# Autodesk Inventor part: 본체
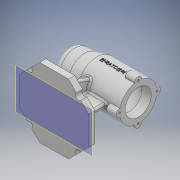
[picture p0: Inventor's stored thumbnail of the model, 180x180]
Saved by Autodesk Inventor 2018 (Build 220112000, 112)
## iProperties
Created: 2019-12
Part Number: 본체
Material: Generic
Document SubType Name: Modeling
Designer: Administrator
Density: 1 g/cm^3
Appearance: Default
Author: Administrator
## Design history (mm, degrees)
sketch "스케치1"
  geometry: L1 (0, 0)-(112, 0); L2 (0, 0)-(0, 25); L3 (0, 25)-(25, 25); L4 (25, 25)-(45, 30); L5 (45, 30)-(112, 30); L6 (112, 30)-(112, 0)
  constraints: 12 end point, 2 perpendicular, 1 horizontal, 1 parallel, 1 vertical
  dimensions: "d0" = 112 distance of L1.start L1.end; "d1" = 25 distance of L1.start L2.end; "d2" = 25 distance of L2.end L3.end; "d3" = 60 diameter of L5 L1; "d4" = 45 distance from line of L4.end L2
revolve "회전1" sketch "스케치1" stored, may be unused: angle "d5" = 90 deg
sketch "스케치2"
  geometry: L1 (112, -30)-(112, 30) reference; L2 (112, 0)-(97, 0); L3 (97, 0)-(97, 21); L4 (97, 21)-(112, 21); L5 (112, 21)-(112, 0); L6 (97, 0)-(43, 0); L7 (43, 0)-(43, 24); L8 (43, 24)-(97, 24); L9 (97, 24)-(97, 0); L10 (43, 0)-(31, 0); L11 (31, 0)-(31, 21); L12 (31, 21)-(43, 21); L13 (43, 21)-(43, 0); L14 (31, 0)-(13, 0); L15 (13, 0)-(13, 17.5); L16 (13, 17.5)-(31, 17.5); L17 (31, 17.5)-(31, 0); L18 (13, 0)-(9, 0); L19 (9, 0)-(9, 16); L20 (9, 16)-(13, 16); L21 (13, 16)-(13, 0); L22 (9, 0)-(6, 0); L23 (6, 0)-(6, 10.5); L24 (6, 10.5)-(9, 10.5); L25 (9, 10.5)-(9, 0); 1 further point
  constraints: 48 end point, 12 parallel, 6 horizontal, 6 perpendicular, 1 midpoint
  dimensions: "d6" = 42 diameter of L4 L2; "d7" = 48 diameter of L8 L6; "d8" = 42 diameter of L12 L10; "d9" = 35 diameter of L16 L14; "d10" = 32 diameter of L20 L18; "d11" = 21 diameter of L24 L22; "d12" = 54 distance between parallel lines of L3 L13; "d13" = 15 distance between parallel lines of L3 L1; "d14" = 12 distance between parallel lines of L13 L17; "d15" = 18 distance between parallel lines of L17 L21; "d16" = 3 distance of L23.end L24.end; "d17" = 4 distance of L19.end L20.end
revolve "회전2" sketch "스케치2" stored, may be unused: angle "d18" = 90 deg
node "작업 평면1"
sketch "스케치3"
  geometry: L1 (-112, 30)-(-112, -30) reference; L2 (-112, 23.196)-(-79.196, 56); L3 (-79.196, 56)-(-32.804, 56); L4 (-32.804, 56)-(0, 23.196); L5 (0, 23.196)-(0, -23.196); L6 (0, -23.196)-(-32.804, -56); L7 (-32.804, -56)-(-79.196, -56); L8 (-79.196, -56)-(-112, -23.196); L9 (-112, -23.196)-(-112, 23.196); C1 r 56 at (-56, 0); 3 further points
  constraints: 16 end point, 2 midpoint, 1 centre point, 1 coincident, 1 tangent, 17 other
  dimensions: "d20" = 112 diameter of C1
extrude "돌출1" join sketch "스케치3" distance "d21" = 10; taper "d22" = 0 deg
sketch "스케치5"
  geometry: C1 r 6 at (0, 30); C2 r 6 at (30, 0); C3 r 6 at (0, -30); C4 r 6 at (-30, 0); A1 r 30 centre (0, 0) between (0, 30) and (30, 0) reference; 1 further point
  constraints: 4 centre point, 4 point on circle
  dimensions: "d27" = 12 diameter of C1; "d28" = 12 diameter of C2; "d29" = 12 diameter of C3; "d30" = 12 diameter of C4
extrude "돌출2" join sketch "스케치5" distance "d31" = 16; taper "d32" = 0 deg
node "작업 평면2"
sketch "스케치6"
  geometry: L1 (-70, 56)-(-70, 23.196) reference; L2 (-70, 56)-(-70, 36); L3 (-70, -56)-(-70, -36); L4 (-70, -56)-(-70, -23.196) reference; L5 (-70, 36)-(-23.234, 18.979); L6 (-70, -36)-(-23.234, -18.979); L7 (-70, -36)-(-70, 36); L8 (-70, 23.196)-(-70, 56) reference; A1 r 30 centre (0, 0) between (-23.234, 18.979) and (-23.234, -18.979); 2 further points
  constraints: 10 end point, 2 point on circle, 2 point on line, 1 centre point, 1 coincident, 1 collinear
  dimensions: "d34" = 20 distance of L1.start L2.end; "d35" = 20 distance of L3.start L3.end; "d37" = 110 deg angle of L1 L5; "d38" = 110 deg angle of L3 L6; "d39" = 60 diameter of A1
extrude "돌출3" join sketch "스케치6" stored distance "d40" = 8; taper "d41" = 0 deg
sketch "스케치7"
  geometry: L1 (60, 36)-(60, -36) reference; L2 (60, 4)-(91, 4); L3 (60, -4)-(91, -4); L4 (91, -4)-(91, 4); L5 (60, -4)-(60, 4); 1 further point
  constraints: 8 end point, 1 collinear, 1 perpendicular
extrude "돌출4" join sketch "스케치7" stored distance "d45" = 8; taper "d46" = 0 deg
sketch "스케치9"
  geometry: L1 (0, -80)-(0, -70) reference; L2 (0, -70)-(32.804, -70) reference; L3 (18, -70)-(37.712, -27.727); L4 (18, -70)-(52, -70); 1 further point
  constraints: 4 end point, 1 horizontal, 1 point on line
  dimensions: "d47" = 18 distance of L1.end L3.start; "d49" = 115 deg angle of L2 L3
feature "리브1" sketch "스케치9" dims "d50" = 1, "d51" = 8, "d52" = 0, "d53" = 0, "d54" = 1, "d55" = 1
fillet "모깎기1" dims "d56" = 10
fillet "모깎기2" dims "d57" = 1
fillet "모깎기3" dims "d58" = 3
sketch "스케치10"
  geometry: L1 (112, -23.196)-(79.196, -56) reference; L2 (32.804, -56)-(0, -23.196) reference; L3 (0, 23.196)-(32.804, 56) reference; L4 (79.196, 56)-(112, 23.196) reference; C1 r 5 at (95.598, -39.598); C2 r 5 at (16.402, -39.598); C3 r 5 at (16.402, 39.598); C4 r 5 at (95.598, 39.598); 1 further point
  constraints: 4 centre point, 4 midpoint
  dimensions: "d59" = 10 diameter of C1; "d60" = 10 diameter of C2; "d61" = 10 diameter of C3; "d62" = 10 diameter of C4
extrude "돌출5" cut sketch "스케치10" distance "d63" = 10; taper "d64" = 0 deg
node "작업 평면3"
sketch "스케치12"
  geometry: L1 (112, 6)-(112, -6) reference; L2 (112, 0)-(71, 0); 4 further points
  constraints: 2 end point, 1 coincident, 1 horizontal, 1 midpoint, 1 other
  dimensions: "d66" = 41 distance of L2.start L2.end
sketch "스케치13"
  geometry: A1 r 5 centre (30, 30) between (34.983, 29.583) and (25.017, 29.583) reference; A2 r 5 centre (0, 0) between (0.417, 4.983) and (0.417, -4.983) reference; A3 r 6 centre (60, 0) between (59.4, -5.97) and (59.4, 5.97) reference; A4 r 6 centre (30, -30) between (24.03, -29.4) and (35.97, -29.4) reference; 5 further points
  constraints: 4 coincident
hole "구멍1" sketch "스케치13" at (30, 30), (60, 0), (0, 0), (30, -30) diameter "d69" = 3.242; stored, may be unused: countersink angle "d73" = 90 deg, drill point angle "d75" = 118 deg; dims "d70" = 8, "d71" = 4, "d72" = 2, "d74" = 11
feature "엠보싱2" dims "d0" = 112, "d1" = 25, "d2" = 25, "d3" = 60, "d4" = 45, "d76" = 0.5, "d77" = 0
node "솔리드1"
other parameters: "d33" = 56
